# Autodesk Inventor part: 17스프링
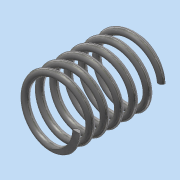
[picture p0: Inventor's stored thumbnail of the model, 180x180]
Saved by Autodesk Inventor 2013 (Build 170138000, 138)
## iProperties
Created: 2019-07
Part Number: 17스프링
Material: 강철, 탄소
Document SubType Name: Modeling
Designer: Administrator
Density: 7.87 g/cm^3
Mass: 7.7901 g
Surface Area: 20.0705 cm^2
Volume: 0.989848 cm^3
Author: Administrator
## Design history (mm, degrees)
sketch "스케치1"
  geometry: L1 (0, 0)-(0, 25.33); L2 (0, 0)-(8.5, 0); L3 (0, 25.33)-(8.5, 25.33); C1 r 1 at (8.5, 0)
  constraints: 6 end point, 2 parallel, 1 centre point, 1 coincident, 1 perpendicular, 1 vertical
  dimensions: "d0" = 25.33013 distance of L1.start L1.end (derived); "d1" = 2 diameter of C1; "d2" = 17 diameter of C1.centre L1
feature "코일1" sketch "스케치1" pitch "d3" = 10; turns "d5" = 6; dims "d4" = 25.33013 (= d0), "d6" = 0, angle "d7" = 90 deg, angle "d8" = 90 deg, "d9" = 0, "d10" = 0
sketch "스케치2"
  geometry: L1 (25.33, 15)-(0, 15); L2 (0, 15)-(0, -15); L3 (0, -15)-(25.33, -15); L4 (25.33, -15)-(25.33, 15); 2 further points
  constraints: 8 end point, 2 parallel, 1 coincident, 1 horizontal, 1 midpoint, 1 perpendicular
  dimensions: "d11" = 30 distance of L3.end L1.start; "d13" = 25.33013 distance of L2.end L3.end (= d0)
extrude "돌출1" sketch "스케치2" stored distance "d14" = 10; taper "d15" = 0 deg
node "솔리드1"
